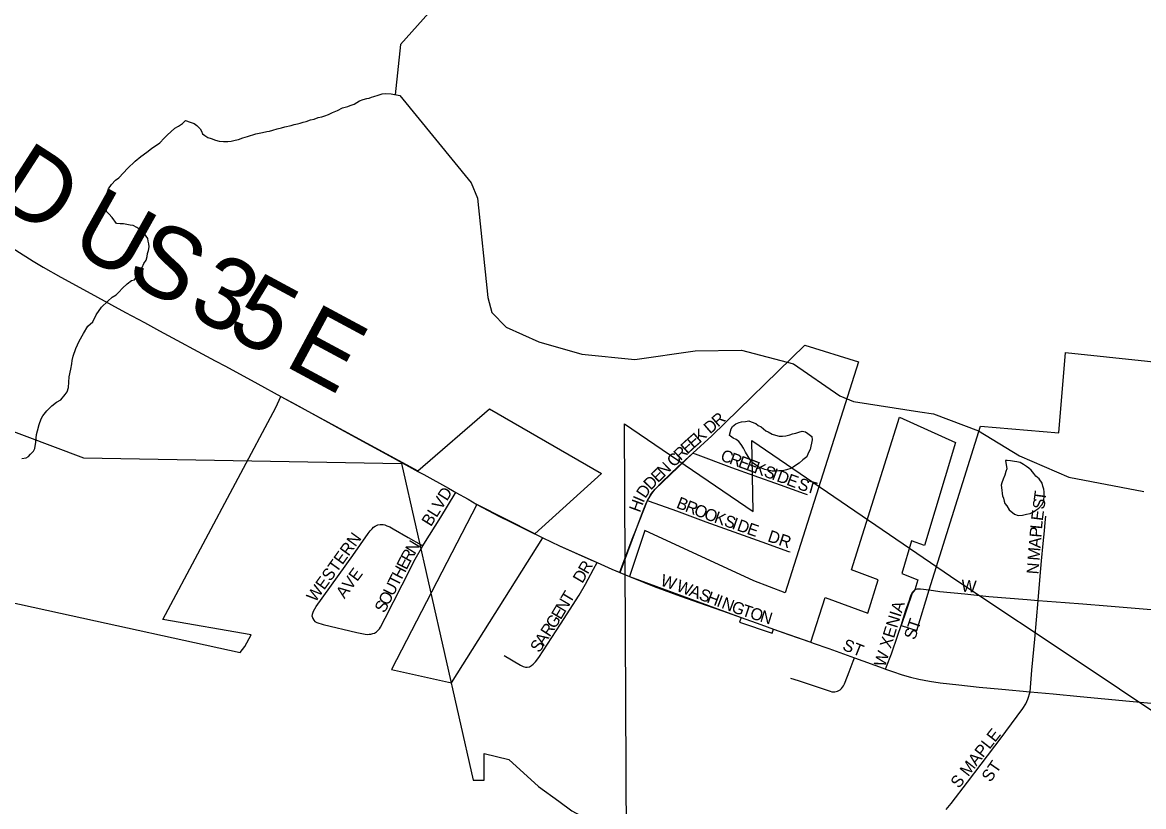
# Model space of a CAD drawing. Extents: x -5.4 to 49.9, y 13.2 to 48.4.
# Drawn here: x 28.445 to 29.333, y 43.576 to 44.197 of the extents above; entities that cross this region are included whole.
import ezdxf

# ---------------------------------------------------------------- set-up
doc = ezdxf.new("R2010")
doc.units = 0
for name, color, linetype in [('GM_X_City_Street', 7, 'Continuous'), ('GM_X_City_Street_Text', 7, 'Continuous'), ('GM_X_Corporation', 7, 'Continuous'), ('GM_X_County_Road', 7, 'Continuous'), ('GM_X_County_Road_Text', 7, 'Continuous'), ('GM_X_Major_River', 7, 'Continuous'), ('GM_X_Minor_Lake', 7, 'Continuous'), ('GM_X_Minor_River', 7, 'Continuous'), ('GM_X_Township_Road', 7, 'Continuous')]:
    doc.layers.add(name, color=color, linetype=linetype)

msp = doc.modelspace()

# ---------------------------------------------------------------- linework, layer by layer
at = {"layer": 'GM_X_City_Street'}
for points in [[(28.97622, 43.85565), (28.99121, 43.86942)], [(28.94018, 43.81818), (28.94119, 43.82009), (28.94272, 43.82255), (28.94438, 43.82488), (28.94632, 43.82705), (28.95148, 43.83256), (28.96462, 43.84499), (28.97622, 43.85565)], [(28.97622, 43.85565), (28.97808, 43.85496), (29.00668, 43.84437), (29.02454, 43.83792), (29.04528, 43.83044), (29.06434, 43.82355), (29.06671, 43.82284)], [(28.75826, 43.84117), (28.76288, 43.83864), (28.78241, 43.82778), (28.78565, 43.82596), (28.78825, 43.82451)], [(28.76214, 43.78215), (28.76286, 43.7834), (28.77645, 43.80495), (28.78776, 43.82369), (28.78825, 43.82451)], [(28.78825, 43.82451), (28.7981, 43.81906), (28.80508, 43.81505)], [(28.91819, 43.76109), (28.91906, 43.76338), (28.92801, 43.78738), (28.93142, 43.79602), (28.93667, 43.81006), (28.93933, 43.81654), (28.94018, 43.81818)], [(28.94018, 43.81818), (28.94146, 43.81772), (28.96331, 43.80988), (28.98654, 43.80126), (29.03094, 43.78529), (29.05198, 43.77776), (29.05316, 43.77737)], [(29.24983, 43.73898), (29.25152, 43.75816), (29.25249, 43.77038), (29.25377, 43.78405), (29.25477, 43.79396), (29.25544, 43.8007), (29.25592, 43.8056)], [(28.67455, 43.72632), (28.67464, 43.72818), (28.67546, 43.7305), (28.67772, 43.73418), (28.7066, 43.77461), (28.71876, 43.79187), (28.72057, 43.794), (28.72197, 43.79566), (28.72322, 43.79689), (28.7243, 43.79771), (28.72538, 43.79837), (28.72651, 43.79883), (28.72832, 43.79924), (28.73079, 43.79916), (28.73216, 43.79881), (28.73373, 43.79818), (28.73592, 43.79714), (28.73871, 43.79565), (28.75067, 43.78872), (28.76083, 43.7829), (28.76214, 43.78215)], [(28.67455, 43.72632), (28.67502, 43.72466), (28.6757, 43.72341), (28.6766, 43.72234), (28.67808, 43.72152), (28.68314, 43.71983), (28.70981, 43.71367), (28.71652, 43.71228), (28.71811, 43.71207), (28.71959, 43.71215), (28.72107, 43.71231), (28.72266, 43.71269), (28.72387, 43.71313), (28.72535, 43.71412), (28.72677, 43.71536), (28.72781, 43.7165), (28.72871, 43.7178), (28.73239, 43.725), (28.74573, 43.75122), (28.75608, 43.77153), (28.76214, 43.78215)], [(28.82664, 43.69523), (28.83947, 43.68756), (28.84175, 43.68658), (28.84355, 43.68612), (28.84478, 43.68607), (28.84659, 43.68648), (28.84825, 43.68731), (28.84971, 43.68845), (28.85141, 43.69026), (28.854, 43.69377), (28.87136, 43.72022), (28.88602, 43.74326), (28.89106, 43.75181), (28.8975, 43.76385), (28.90021, 43.76892)], [(28.91205, 43.76368), (28.91819, 43.76109)], [(28.91819, 43.76109), (28.92587, 43.75784), (28.93693, 43.75336), (28.9455, 43.75003), (28.96639, 43.74231), (28.98679, 43.73512), (28.99962, 43.73059), (29.01456, 43.72531), (29.03003, 43.71981), (29.03998, 43.71627), (29.05194, 43.71202), (29.06966, 43.70582), (29.07154, 43.70517)], [(29.16355, 43.74728), (29.17188, 43.7461), (29.1918, 43.74407), (29.21078, 43.74213), (29.24111, 43.73967), (29.24983, 43.73898)], [(29.24355, 43.66654), (29.24491, 43.6836), (29.2471, 43.70822), (29.24983, 43.73898)], [(29.24983, 43.73898), (29.27129, 43.73729), (29.28533, 43.73616), (29.30456, 43.73463), (29.34875, 43.7311), (29.38528, 43.72763), (29.43332, 43.72308), (29.45313, 43.7213), (29.47914, 43.71897)], [(29.12893, 43.68453), (29.1297, 43.6866), (29.13346, 43.69671), (29.13867, 43.71152), (29.14122, 43.71909)], [(29.07154, 43.70517), (29.08384, 43.70092), (29.10428, 43.69347)], [(29.05363, 43.67744), (29.05954, 43.67549), (29.07304, 43.67101), (29.08511, 43.66701), (29.0864, 43.66668), (29.08777, 43.66655), (29.08875, 43.66656), (29.08985, 43.6667), (29.09086, 43.66701), (29.0918, 43.66748), (29.09292, 43.66824), (29.09394, 43.66922), (29.09481, 43.67022), (29.09556, 43.67138), (29.09637, 43.67293), (29.09697, 43.67434), (29.10006, 43.68242), (29.10324, 43.69076), (29.10428, 43.69347)], [(29.10428, 43.69347), (29.1269, 43.68523), (29.12893, 43.68453)], [(29.12893, 43.68453), (29.13448, 43.68259), (29.14209, 43.67998), (29.1486, 43.67808), (29.1552, 43.67658), (29.16369, 43.67491), (29.17225, 43.67358), (29.18705, 43.67197), (29.20305, 43.67028), (29.22096, 43.66864), (29.24355, 43.66654)], [(29.18074, 43.5781), (29.19369, 43.59511), (29.20475, 43.6093), (29.22058, 43.63014), (29.22418, 43.63523), (29.23756, 43.65322), (29.23998, 43.65715), (29.24164, 43.66077), (29.24355, 43.66654)], [(29.24355, 43.66654), (29.26162, 43.66485), (29.28321, 43.66283), (29.32215, 43.65912), (29.35921, 43.65567), (29.39677, 43.65238), (29.43323, 43.64891), (29.47219, 43.64552)], [(29.17703, 43.57322), (29.18074, 43.5781)]]:
    msp.add_lwpolyline(points, dxfattribs=at)
at = {"layer": 'GM_X_Corporation'}
for points in [[(28.19911, 43.96243), (28.49325, 43.85199), (28.74526, 43.84756), (28.80204, 43.59652), (28.81076, 43.59653), (28.81073, 43.61765), (28.83035, 43.61293), (28.85386, 43.59166), (28.87001, 43.57987), (28.88039, 43.57229), (28.90678, 43.55803), (28.92368, 43.5489), (28.9219, 43.87882), (29.02409, 43.80942), (29.02303, 43.86557), (29.18623, 43.75426), (29.28308, 43.68973), (29.34531, 43.6481)], [(28.43166, 43.73848), (28.47498, 43.72897), (28.61752, 43.69763), (28.62112, 43.70245), (28.62622, 43.71162), (28.5562, 43.72393), (28.64574, 43.89172), (28.6497, 43.90052), (28.75835, 43.84169), (28.81505, 43.89064), (28.9037, 43.83941), (28.85101, 43.79165), (28.80508, 43.81504), (28.73738, 43.68415), (28.78491, 43.67363), (28.85719, 43.78863), (28.8706, 43.78228), (28.90021, 43.76892), (28.91205, 43.76368), (28.91847, 43.76097), (28.93142, 43.79603), (28.94019, 43.81817), (28.94355, 43.82372), (28.94632, 43.82705), (28.97622, 43.85565), (28.99121, 43.86942), (29.06488, 43.94105), (29.10738, 43.92797), (29.04922, 43.74495), (29.02455, 43.75447), (28.93815, 43.79425), (28.92587, 43.75784), (29.01456, 43.72531), (29.01314, 43.72172), (29.03889, 43.71295), (29.03998, 43.71626), (29.06966, 43.70582), (29.08099, 43.74135), (29.11472, 43.72878), (29.123, 43.7554), (29.1019, 43.76315), (29.13998, 43.88405), (29.18429, 43.86417), (29.15964, 43.78247), (29.1494, 43.78605), (29.14173, 43.76036), (29.15446, 43.75523), (29.15201, 43.74744), (29.14987, 43.7447), (29.14122, 43.71909), (29.1536, 43.71524), (29.16355, 43.74728), (29.2041, 43.87708), (29.26622, 43.8716), (29.27149, 43.93527), (29.49891, 43.91137)]]:
    msp.add_lwpolyline(points, dxfattribs=at)
at = {"layer": 'GM_X_County_Road'}
for points in [[(28.18075, 44.18898), (28.18524, 44.18594), (28.21574, 44.16563), (28.22818, 44.1574), (28.25804, 44.13728), (28.2747, 44.12641), (28.28757, 44.11776), (28.30659, 44.10508), (28.34212, 44.08122), (28.39921, 44.04332), (28.42124, 44.02871), (28.42731, 44.02445), (28.43403, 44.02002), (28.43975, 44.01631), (28.45333, 44.00768), (28.46131, 44.00292), (28.47535, 43.995), (28.49332, 43.98515), (28.52664, 43.96713), (28.54151, 43.95908)], [(28.54151, 43.95908), (28.55341, 43.95265), (28.5977, 43.92882), (28.6059, 43.92441), (28.63152, 43.91053), (28.6497, 43.90052)], [(28.6497, 43.90052), (28.66092, 43.89454), (28.67398, 43.88737), (28.70283, 43.87156), (28.73872, 43.8519), (28.75826, 43.84117)], [(28.80508, 43.81505), (28.82298, 43.80555), (28.83125, 43.8014), (28.84482, 43.79468), (28.85719, 43.78863)], [(28.85719, 43.78863), (28.85733, 43.78857), (28.8706, 43.78229), (28.89522, 43.77113), (28.90021, 43.76892)], [(28.90021, 43.76892), (28.91205, 43.76368)]]:
    msp.add_lwpolyline(points, dxfattribs=at)
at = {"layer": 'GM_X_Major_River'}
for points in [[(28.54488, 44.01606), (28.54529, 44.0191), (28.54493, 44.02138), (28.54458, 44.02366), (28.54422, 44.02556), (28.5416, 44.02939), (28.53972, 44.03131), (28.53784, 44.03285), (28.53558, 44.03439), (28.53256, 44.03594), (28.53029, 44.03634), (28.52764, 44.03675), (28.52499, 44.03716), (28.52233, 44.03719), (28.5193, 44.0376), (28.51593, 44.04219), (28.51331, 44.04526), (28.51143, 44.04717), (28.5111, 44.05212), (28.51113, 44.05553), (28.51116, 44.05819), (28.51156, 44.06009), (28.51196, 44.06198), (28.51313, 44.06501), (28.51545, 44.0684), (28.51852, 44.07179), (28.52119, 44.07366), (28.52503, 44.0778), (28.5281, 44.08119), (28.53424, 44.08682), (28.53883, 44.09057), (28.54342, 44.09394), (28.54724, 44.09694), (28.55374, 44.10143), (28.5572, 44.10519), (28.55988, 44.10783), (28.56256, 44.11008), (28.56563, 44.11308), (28.56868, 44.11457), (28.57174, 44.11682), (28.57404, 44.11908), (28.57782, 44.1179), (28.58085, 44.11673), (28.58311, 44.11518), (28.58574, 44.1125), (28.58685, 44.11059), (28.5876, 44.10868), (28.58948, 44.10714), (28.59174, 44.1056), (28.59438, 44.10481), (28.59779, 44.10364), (28.60081, 44.10284), (28.60423, 44.10243), (28.60764, 44.1024), (28.6103, 44.10275), (28.61335, 44.10348), (28.61601, 44.10421), (28.61944, 44.10531), (28.62324, 44.10641), (28.62972, 44.10862), (28.63504, 44.10971), (28.63847, 44.11043), (28.64075, 44.11079), (28.64341, 44.11152), (28.64684, 44.11262), (28.65026, 44.11335), (28.65292, 44.11408), (28.65787, 44.11517), (28.66016, 44.1159), (28.66282, 44.11664), (28.6651, 44.11699), (28.66738, 44.11773), (28.66967, 44.11847), (28.6731, 44.11957), (28.67614, 44.1203), (28.67919, 44.12141), (28.68223, 44.12213), (28.68452, 44.12287), (28.68756, 44.12398), (28.69062, 44.12547), (28.69443, 44.12695), (28.69863, 44.12918), (28.70281, 44.13028), (28.70472, 44.13102), (28.70777, 44.13212), (28.71196, 44.13474), (28.71501, 44.13585), (28.71768, 44.13658), (28.71958, 44.13694), (28.72148, 44.13768), (28.72338, 44.13804), (28.72681, 44.13915), (28.72986, 44.14025), (28.7329, 44.1406), (28.73707, 44.14018), (28.744, 44.13897)], [(28.744, 44.13897), (28.80051, 44.06984), (28.80556, 44.05759), (28.81382, 43.97885), (28.81699, 43.96701), (28.82811, 43.9554), (28.85398, 43.94387), (28.88821, 43.93406), (28.93012, 43.92979), (28.97793, 43.9368), (29.01463, 43.93719), (29.05603, 43.92648), (29.0926, 43.90106), (29.10349, 43.89666), (29.15591, 43.88839), (29.16685, 43.88665), (29.20252, 43.8734), (29.23503, 43.85338), (29.27405, 43.83664), (29.33359, 43.82519)], [(28.44448, 43.85149), (28.4479, 43.85184), (28.44981, 43.85296), (28.45135, 43.85484), (28.45365, 43.8571), (28.45481, 43.85936), (28.45562, 43.86429), (28.45606, 43.87037), (28.45685, 43.8734), (28.45804, 43.87832), (28.45961, 43.88286), (28.46115, 43.88513), (28.46423, 43.88927), (28.46806, 43.89303), (28.47189, 43.89603), (28.47533, 43.89789), (28.47879, 43.90204), (28.48033, 43.9043), (28.4815, 43.9077), (28.48197, 43.91606), (28.48317, 43.92212), (28.48397, 43.92629), (28.48438, 43.92894), (28.48517, 43.93236), (28.48714, 43.93841), (28.48986, 43.94446), (28.49334, 43.9505), (28.49681, 43.95616), (28.50064, 43.95954), (28.50336, 43.96521), (28.5076, 43.97125), (28.51258, 43.97613), (28.51603, 43.97914), (28.51908, 43.981), (28.52138, 43.98326), (28.52407, 43.98627), (28.5279, 43.98965), (28.53134, 43.99227), (28.53363, 43.99301), (28.53517, 43.99527), (28.53749, 43.99942), (28.5398, 44.00282), (28.54097, 44.00584), (28.5429, 44.00848), (28.54369, 44.01151), (28.54409, 44.01379), (28.54488, 44.01606)]]:
    msp.add_lwpolyline(points, dxfattribs=at)
at = {"layer": 'GM_X_Minor_Lake'}
for points in [[(29.00662, 43.875), (29.00748, 43.87668), (29.01016, 43.87893), (29.01283, 43.88004), (29.01473, 43.8804), (29.01777, 43.88075), (29.02043, 43.8811), (29.02232, 43.88032), (29.0261, 43.87913), (29.02798, 43.87759), (29.03024, 43.87643), (29.03213, 43.87489), (29.03401, 43.87335), (29.03589, 43.87256), (29.03891, 43.87063), (29.04156, 43.86984), (29.04458, 43.86905), (29.04724, 43.86902), (29.0499, 43.86937), (29.05294, 43.87009), (29.05523, 43.87083), (29.05789, 43.87156), (29.06017, 43.87229), (29.06284, 43.87302), (29.06549, 43.87261), (29.06737, 43.87107), (29.07038, 43.86876), (29.07073, 43.86609), (29.06913, 43.85851), (29.06759, 43.85549), (29.06642, 43.85284), (29.06335, 43.85022), (29.06029, 43.84759), (29.05762, 43.84572), (29.05571, 43.8446), (29.0538, 43.84349), (29.05037, 43.84238), (29.04733, 43.84166), (29.04429, 43.84169), (29.04201, 43.84134), (29.03898, 43.84137), (29.03557, 43.84217), (29.0333, 43.84258), (29.03066, 43.84375), (29.02801, 43.84491), (29.02575, 43.84646), (29.02387, 43.84762), (29.02162, 43.85031), (29.02013, 43.85298), (29.01789, 43.85643), (29.01641, 43.85948), (29.01454, 43.86255), (29.01267, 43.86484), (29.01041, 43.86639), (29.00814, 43.86756), (29.00588, 43.8691), (29.00513, 43.86949), (29.00513, 43.86987)], [(29.00513, 43.86987), (29.00662, 43.875)], [(29.22385, 43.84993), (29.22492, 43.84308), (29.22414, 43.84119), (29.22335, 43.83815), (29.22217, 43.83513), (29.221, 43.8321), (29.2206, 43.83021), (29.22094, 43.8264), (29.2213, 43.82374), (29.22165, 43.82184), (29.22239, 43.81993), (29.22275, 43.81764), (29.22349, 43.81574), (29.22499, 43.81382), (29.22685, 43.81076), (29.23099, 43.80729), (29.23401, 43.80612), (29.23743, 43.80646), (29.24047, 43.80719), (29.24351, 43.80791), (29.24618, 43.80902), (29.24809, 43.81052), (29.25039, 43.81201), (29.25269, 43.81465), (29.25424, 43.81767), (29.25467, 43.82223), (29.2547, 43.82488), (29.25434, 43.82717), (29.25361, 43.82946), (29.25287, 43.83174), (29.25063, 43.83519), (29.248, 43.8375), (29.2465, 43.83942), (29.24425, 43.8421), (29.24237, 43.84364), (29.24049, 43.84518), (29.23823, 43.84673), (29.2356, 43.84828), (29.23294, 43.84869), (29.23105, 43.84909), (29.22802, 43.8495), (29.22537, 43.84991), (29.22385, 43.84993)]]:
    msp.add_lwpolyline(points, dxfattribs=at)
at = {"layer": 'GM_X_Minor_River'}
for points in [[(28.74461, 44.17935), (28.77601, 44.21465), (28.78798, 44.24862), (28.81641, 44.29178), (28.8365, 44.31306), (28.85559, 44.32145), (28.86624, 44.32316), (28.91181, 44.35043), (28.94304, 44.35898), (28.98093, 44.35867), (29.0212, 44.36439), (29.04291, 44.37045), (29.09641, 44.39569), (29.11829, 44.41124), (29.14888, 44.42626), (29.1735, 44.42581), (29.1848, 44.4218), (29.19613, 44.4197), (29.20597, 44.41914), (29.21552, 44.42314), (29.23991, 44.45233), (29.25683, 44.48735)], [(28.74461, 44.17935), (28.74035, 44.13961)]]:
    msp.add_lwpolyline(points, dxfattribs=at)
at = {"layer": 'GM_X_Township_Road'}
for points in [[(29.14122, 43.71909), (29.14504, 43.73131), (29.14775, 43.73904), (29.14838, 43.74114), (29.14921, 43.74351), (29.15052, 43.7459), (29.15202, 43.74744)], [(29.15202, 43.74744), (29.15296, 43.74788), (29.1537, 43.7481), (29.15533, 43.74823), (29.1567, 43.74809), (29.16355, 43.74728)]]:
    msp.add_lwpolyline(points, dxfattribs=at)

# ---------------------------------------------------------------- texts
at = {"layer": 'GM_X_City_Street_Text'}
for s, rotation, p in [('R', 40.96817, (28.99611, 43.87584)), ('K', 40.96392, (28.98163, 43.86327)), ('D', 40.97035, (28.98982, 43.87038)), ('E', 42.836, (28.97179, 43.8544)), ('E', 41.25016, (28.97663, 43.85889)), ('C', 44.20999, (28.96108, 43.84398)), ('R', 44.23282, (28.96646, 43.84921)), ('C', 339.6912, (28.99737, 43.85012)), ('R', 339.69674, (29.00441, 43.84751)), ('N', 44.21178, (28.95331, 43.83641)), ('E', 339.69015, (29.01144, 43.84491)), ('E', 339.69015, (29.01769, 43.8426)), ('K', 339.69873, (29.02395, 43.84028)), ('E', 44.26597, (28.94854, 43.83176)), ('S', 339.69015, (29.03176, 43.83739)), ('I', 339.68446, (29.03802, 43.83508)), ('D', 339.71298, (29.04193, 43.83363)), ('E', 339.71094, (29.04974, 43.83074)), ('D', 56.44933, (28.93848, 43.81923)), ('D', 46.00454, (28.9428, 43.82582)), ('S', 340.63486, (29.0585, 43.8275)), ('T', 344.18888, (29.06541, 43.82509)), ('BLVD', 57.99522, (28.76858, 43.79689)), ('I', 66.81862, (28.93706, 43.8158)), ('B', 338.23016, (28.96242, 43.8126)), ('T', 82.14037, (29.25555, 43.81733)), ('H', 69.64346, (28.9342, 43.8081)), ('R', 338.20761, (28.96938, 43.80982)), ('O', 338.23179, (28.97635, 43.80704)), ('O', 339.71298, (28.98434, 43.80385)), ('S', 82.13268, (29.25464, 43.81073)), ('K', 340.78814, (28.99234, 43.8009)), ('S', 340.82547, (29.00021, 43.79815)), ('I', 340.84488, (29.00651, 43.79596)), ('D', 340.82548, (29.01045, 43.79459)), ('E', 82.7123, (29.25346, 43.80166)), ('WESTERN', 54.16175, (28.67697, 43.73699)), ('E', 340.82211, (29.01832, 43.79186)), ('DR', 341.56141, (29.03482, 43.78597)), ('P', 85.40428, (29.25231, 43.7885)), ('L', 84.63737, (29.25284, 43.79511)), ('N', 58.63882, (28.7558, 43.77492)), ('A', 85.40515, (29.25164, 43.78019)), ('R', 61.18601, (28.75224, 43.76845)), ('M', 85.40574, (29.25084, 43.77022)), ('H', 62.99674, (28.74547, 43.75515)), ('E', 62.97062, (28.74925, 43.76258)), ('R', 60.16024, (28.89289, 43.75917)), ('N', 85.40515, (29.24997, 43.75942)), ('AVE', 53.5321, (28.70009, 43.73982)), ('T', 62.97062, (28.74243, 43.74921)), ('D', 59.33609, (28.88857, 43.75187)), ('W', 341.57598, (28.94982, 43.75097)), ('U', 62.97549, (28.73865, 43.74179)), ('W', 339.16649, (28.96239, 43.74678)), ('A', 339.15043, (28.97251, 43.74293)), ('W', 355.60387, (29.18855, 43.74605)), ('O', 62.99674, (28.73486, 43.73436)), ('N', 59.36577, (28.87489, 43.7289)), ('T', 59.3502, (28.87914, 43.73607)), ('S', 339.16799, (28.9803, 43.73996)), ('H', 339.15235, (28.98653, 43.73759)), ('I', 339.18512, (28.99433, 43.73462)), ('N', 339.17278, (28.99822, 43.73314)), ('S', 62.97062, (28.73183, 43.72842)), ('E', 59.11327, (28.87145, 43.72314)), ('G', 339.49941, (29.00606, 43.73016)), ('T', 341.77862, (29.01426, 43.7271)), ('O', 342.7259, (29.02076, 43.72496)), ('N', 342.74759, (29.02872, 43.72249)), ('W XENIA', 72.75379, (29.12839, 43.68565)), ('G', 57.56572, (28.86683, 43.71587)), ('ST', 71.57378, (29.15219, 43.7072)), ('R', 56.80056, (28.86265, 43.70948)), ('S', 56.78719, (28.85443, 43.69693)), ('A', 56.78278, (28.85808, 43.7025)), ('ST', 338.19608, (29.09408, 43.7001)), ('S MAPLE', 51.95538, (29.18696, 43.58948)), ('ST', 55.29785, (29.21201, 43.59436))]:
    msp.add_text(s, height=0.00947, rotation=rotation, dxfattribs=at).set_placement(p)
at = {"layer": 'GM_X_County_Road_Text'}
for s, rotation, p in [('D', 327.19276, (28.41997, 44.05654)), ('U', 330.8213, (28.48038, 44.01844)), ('S', 331.71423, (28.52488, 43.9936)), ('3', 331.71186, (28.57405, 43.96713)), ('5', 331.71186, (28.60487, 43.95055)), ('E', 331.71173, (28.6511, 43.92567))]:
    msp.add_text(s, height=0.05682, rotation=rotation, dxfattribs=at).set_placement(p)

doc.saveas('drawing.dxf')
